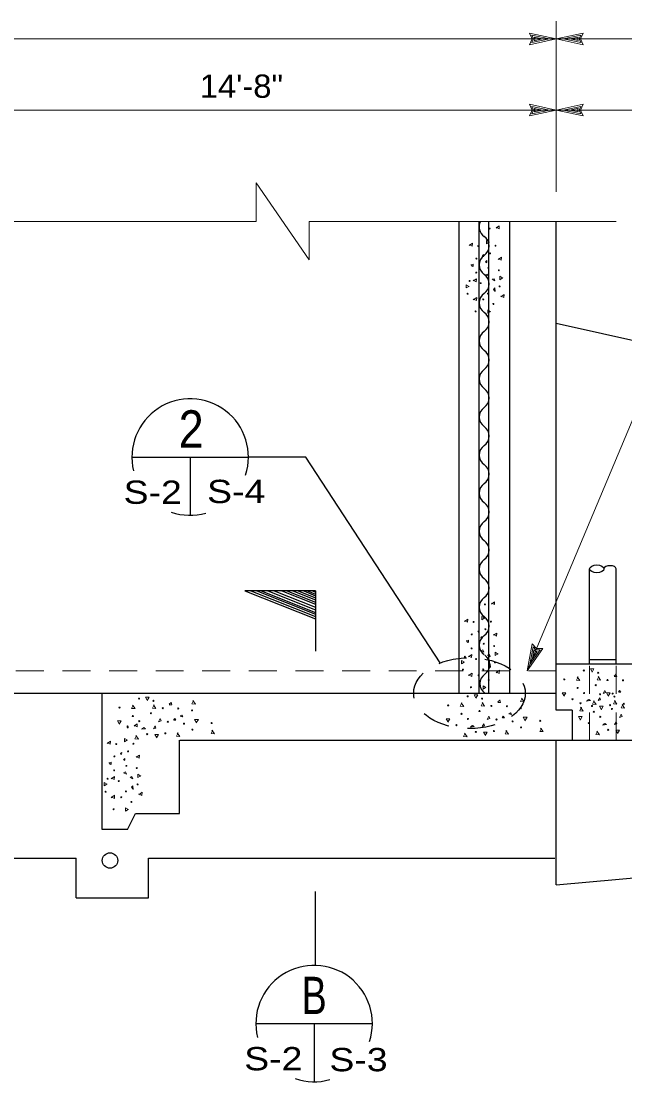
# Model space of a CAD drawing. Extents: x -22.3 to 19.7, y -11.8 to 18.2.
# Drawn here: x -3.89 to -0.65, y 0.55 to 6.24 of the extents above; entities that cross this region are included whole.
import ezdxf
from ezdxf.enums import TextEntityAlignment as Align

# ---------------------------------------------------------------- set-up
doc = ezdxf.new("R2010")
doc.units = 0
doc.header["$LTSCALE"] = 0.05
doc.linetypes.add('MEDIUM_DASHED', pattern=[4.5, 3, -1.5])
doc.layers.add('1', color=7, linetype='Continuous', lineweight=13)
doc.layers.add('2', color=7, linetype='Continuous', lineweight=13)

msp = doc.modelspace()

# ---------------------------------------------------------------- linework, layer by layer
at = {"layer": '1'}
for p, q in [((-1.02142, 5.32831), (-1.02142, 6.24331)), ((-8.42042, 6.14831), (-1.02142, 6.14831)), ((-1.02142, 6.14831), (-1.16542, 6.17931)), ((-1.02142, 6.14831), (-1.16542, 6.11731)), ((-1.05842, 6.14831), (-1.15242, 6.16831)), ((-1.14342, 6.14831), (-1.15242, 6.16831)), ((-1.05842, 6.14831), (-1.15242, 6.12831)), ((-1.15242, 6.12831), (-1.14342, 6.14831)), ((-1.09442, 6.14831), (-1.13942, 6.15731)), ((-1.13542, 6.14831), (-1.13942, 6.15731)), ((-1.09442, 6.14831), (-1.13942, 6.13831)), ((-1.13942, 6.13831), (-1.13542, 6.14831)), ((-1.02142, 6.14831), (-0.87742, 6.17931)), ((-1.02142, 6.14831), (-0.87742, 6.11731)), ((-1.02142, 6.14831), (4.89858, 6.14831)), ((-0.98442, 6.14831), (-0.89042, 6.16831)), ((-0.98442, 6.14831), (-0.89042, 6.12831)), ((-0.94842, 6.14831), (-0.90342, 6.15831)), ((-0.94842, 6.14831), (-0.90342, 6.13931)), ((-0.90342, 6.15831), (-0.90742, 6.14831)), ((-0.90742, 6.14831), (-0.90342, 6.13931)), ((-0.89042, 6.16831), (-0.89942, 6.14831)), ((-0.89942, 6.14831), (-0.89042, 6.12831)), ((-1.02142, 5.76631), (-1.16542, 5.79731)), ((-1.02142, 5.76631), (-1.16542, 5.73531)), ((-1.05842, 5.76631), (-1.15242, 5.78631)), ((-1.14342, 5.76631), (-1.15242, 5.78631)), ((-1.05842, 5.76631), (-1.15242, 5.74631)), ((-1.15242, 5.74631), (-1.14342, 5.76631)), ((-1.09442, 5.76631), (-1.13942, 5.77531)), ((-1.13542, 5.76631), (-1.13942, 5.77531)), ((-1.09442, 5.76631), (-1.13942, 5.75631)), ((-1.13942, 5.75631), (-1.13542, 5.76631)), ((-1.02142, 5.76631), (-0.87742, 5.79731)), ((-1.02142, 5.76631), (-0.87742, 5.73531)), ((-1.02142, 5.76631), (4.88358, 5.76631)), ((-0.98442, 5.76631), (-0.89042, 5.78631)), ((-0.98442, 5.76631), (-0.89042, 5.74631)), ((-0.94842, 5.76631), (-0.90342, 5.77631)), ((-0.94842, 5.76631), (-0.90342, 5.75731)), ((-0.90342, 5.77631), (-0.90742, 5.76631)), ((-0.90742, 5.76631), (-0.90342, 5.75731)), ((-0.89042, 5.78631), (-0.89942, 5.76631)), ((-0.89942, 5.76631), (-0.89042, 5.74631)), ((-2.63142, 5.16931), (-2.63142, 5.37531)), ((-2.34642, 4.96231), (-2.63142, 5.37531)), ((-4.53142, 5.16931), (-2.63142, 5.16931)), ((-2.34642, 4.96231), (-2.34642, 5.16931)), ((-2.34642, 5.16931), (-0.69942, 5.16931)), ((-1.17742, 2.75631), (-1.09342, 2.87731)), ((-1.16342, 2.79031), (-1.14542, 2.88531)), ((-1.16342, 2.79031), (-1.10842, 2.86931)), ((-1.14942, 2.82331), (-1.14142, 2.86931)), ((-1.14942, 2.82331), (-1.12342, 2.86131)), ((-1.14542, 2.88531), (-1.13042, 2.86931)), ((-1.14142, 2.86931), (-1.13342, 2.86131)), ((-1.13342, 2.86131), (-1.12342, 2.86131)), ((-1.13042, 2.86931), (-1.10842, 2.86931))]:
    msp.add_line(p, q, dxfattribs=at)
at = {"layer": '1', "lineweight": 25}
for p, q in [((-1.54242, 2.63731), (-1.54242, 5.16931)), ((-1.43542, 2.63731), (-1.43542, 5.16931)), ((-1.38242, 2.63731), (-1.38242, 5.16931)), ((-1.27142, 2.63731), (-1.27142, 5.16931)), ((-1.02142, 2.54631), (-1.02142, 5.16931)), ((-1.02142, 4.62231), (1.75058, 4.00831)), ((-0.84242, 2.79431), (-0.84242, 3.30431)), ((-0.70042, 2.79431), (-0.70042, 3.30431)), ((-1.02142, 2.79431), (0.96858, 2.79431)), ((-0.84242, 2.81831), (-0.70042, 2.81831)), ((-8.42042, 2.63731), (-1.02142, 2.63731)), ((-3.45742, 1.90531), (-3.45742, 2.63731)), ((-0.93642, 2.54631), (-1.02142, 2.54631)), ((-0.93642, 2.54631), (-0.93642, 2.38331)), ((-3.04242, 1.99231), (-3.04242, 2.38431)), ((-3.04142, 2.38431), (1.73958, 2.38431)), ((-1.02142, 1.60831), (-1.02142, 2.38431)), ((-3.32242, 1.90531), (-3.27842, 1.99231)), ((-3.27842, 1.99231), (-3.04242, 1.99231)), ((-3.32242, 1.90531), (-3.45742, 1.90531)), ((-1.02142, 1.60831), (1.74758, 1.85831)), ((-5.83442, 1.75131), (-3.59642, 1.75131)), ((-3.59642, 1.53931), (-3.59642, 1.75131)), ((-3.20842, 1.75131), (-1.02942, 1.75131)), ((-3.20842, 1.53931), (-3.20842, 1.75131)), ((-3.59642, 1.53931), (-3.20842, 1.53931))]:
    msp.add_line(p, q, dxfattribs=at)
at = {"layer": '1', "linetype": 'MEDIUM_DASHED'}
for p, q in [((-0.84242, 2.38431), (-0.84242, 2.79431)), ((-0.70042, 2.38431), (-0.70042, 2.79431)), ((-8.42042, 2.75631), (-1.02142, 2.75631))]:
    msp.add_line(p, q, dxfattribs=at)
at = {"layer": '1'}
for points in [[(-1.16542, 6.11731), (-1.15142, 6.14831), (-1.16542, 6.17931)], [(-0.87742, 6.17931), (-0.89142, 6.14831), (-0.87742, 6.11731)], [(-8.42042, 5.76631), (-4.72742, 5.76631), (-1.02142, 5.76631)], [(-1.16542, 5.73531), (-1.15142, 5.76631), (-1.16542, 5.79731)], [(-0.87742, 5.79731), (-0.89142, 5.76631), (-0.87742, 5.73531)], [(-0.18742, 5.11631), (-1.17742, 2.75631), (-1.15042, 2.90131)], [(-1.15042, 2.90131), (-1.12742, 2.87631), (-1.09342, 2.87731)]]:
    msp.add_lwpolyline(points, dxfattribs=at)
at = {"layer": '1', "lineweight": 25}
msp.add_lwpolyline([(-1.64342, 2.79931), (-2.36542, 3.90431), (-2.67342, 3.90431)], dxfattribs=at)
msp.add_circle((-3.41542, 1.73931), 0.0412, dxfattribs=at)
for centre, start, end in [((-1.37392, 5.13931), 152.03288, 235.92281), ((-1.44292, 5.03731), 304.0772, 55.92281), ((-1.37392, 4.93531), 124.0772, 235.92281), ((-1.44292, 4.83331), 304.0772, 55.92281), ((-1.37392, 4.73131), 124.0772, 235.92281), ((-1.44292, 4.62931), 304.0772, 55.92281), ((-1.37392, 4.52731), 124.0772, 235.92281), ((-1.44292, 4.42531), 304.0772, 55.92281), ((-1.37392, 4.32331), 124.0772, 235.92281), ((-1.44292, 4.22131), 304.0772, 55.92281), ((-1.37392, 4.11931), 124.0772, 235.92281), ((-1.44292, 4.01731), 304.0772, 55.92281), ((-1.37392, 3.91531), 124.0772, 235.92281), ((-1.44292, 3.81331), 304.0772, 55.92281), ((-1.37392, 3.71131), 124.0772, 235.92281), ((-1.44292, 3.60931), 304.0772, 55.92281), ((-1.37392, 3.50731), 124.0772, 235.92281), ((-1.44292, 3.40531), 304.0772, 55.92281), ((-1.37392, 3.30331), 124.0772, 235.92281), ((-1.44292, 3.20131), 304.0772, 55.92281), ((-1.37392, 3.09931), 124.0772, 235.92281), ((-1.44292, 2.99731), 304.0772, 55.92281), ((-1.37392, 2.89531), 124.0772, 235.92281), ((-1.43892, 2.79031), 304.0772, 55.92281), ((-1.36992, 2.68831), 124.0772, 235.92281)]:
    msp.add_arc(centre, 0.06157, start, end, dxfattribs=at)
msp.add_ellipse((-0.80392, 3.30431), major_axis=(0.0385, 0), ratio=0.545501, dxfattribs=at)
msp.add_ellipse((-0.73292, 3.30431), major_axis=(-0.0325, 0), ratio=0.528164, start_param=3.1415927, end_param=6.2831853, dxfattribs=at)
at = {"layer": '1', "linetype": 'MEDIUM_DASHED', "lineweight": 25}
msp.add_ellipse((-1.48692, 2.63731), major_axis=(0.2995, -0.001), ratio=0.634389, dxfattribs=at)
at = {"layer": '2'}
for p, q in [((-1.47042, 4.92631), (-1.47842, 4.93531)), ((-1.49542, 2.90931), (-1.50342, 2.91831)), ((-0.71142, 2.72931), (-0.70142, 2.73831)), ((-3.09742, 2.57831), (-3.08742, 2.58731)), ((-1.33442, 2.59031), (-1.32442, 2.59931)), ((-3.41242, 2.25431), (-3.42042, 2.26331))]:
    msp.add_line(p, q, dxfattribs=at)
at = {"layer": '2', "lineweight": 25}
for p, q in [((-3.29742, 3.90431), (-2.67342, 3.90431)), ((-2.98542, 3.90431), (-2.98542, 3.59231)), ((-2.66042, 3.18631), (-2.31242, 3.04831)), ((-2.62742, 3.18631), (-2.31242, 3.06131)), ((-2.60442, 3.18631), (-2.31242, 3.07031)), ((-2.56842, 3.18631), (-2.31242, 3.08431)), ((-2.53442, 3.18631), (-2.31242, 3.09831)), ((-2.49342, 3.18631), (-2.31242, 3.11431)), ((-2.46642, 3.18631), (-2.31242, 3.12531)), ((-2.43442, 3.18631), (-2.31242, 3.13731)), ((-2.40542, 3.18631), (-2.31242, 3.14931)), ((-2.37642, 3.18631), (-2.31242, 3.16031)), ((-2.35642, 3.18631), (-2.31242, 3.16831)), ((-2.32942, 3.18631), (-2.31242, 3.17931)), ((-2.31242, 3.18631), (-2.31242, 2.86231)), ((-2.31242, 1.17831), (-2.31242, 1.57331)), ((-2.63242, 0.86431), (-2.00842, 0.86431)), ((-2.32042, 0.86431), (-2.32042, 0.55231))]:
    msp.add_line(p, q, dxfattribs=at)
at = {"layer": '2'}
for points in [[(-1.34442, 5.13731), (-1.32842, 5.12931), (-1.32742, 5.14531), (-1.34442, 5.13231)], [(-1.38342, 5.05731), (-1.39642, 5.04831), (-1.39642, 5.06631), (-1.37942, 5.05731)], [(-1.48842, 5.04331), (-1.47242, 5.03531), (-1.47042, 5.05231), (-1.48842, 5.03931)], [(-1.41442, 4.97931), (-1.41742, 4.98731), (-1.40942, 4.99131), (-1.41242, 4.97931)], [(-1.39342, 4.94731), (-1.40142, 4.95231), (-1.39342, 4.95831), (-1.39342, 4.94931)], [(-1.33242, 4.96831), (-1.31642, 4.96031), (-1.31442, 4.97631), (-1.33242, 4.96531)], [(-1.48042, 4.93531), (-1.46742, 4.93931), (-1.46742, 4.92631)], [(-1.46742, 4.85331), (-1.45142, 4.84531), (-1.44942, 4.86131), (-1.46742, 4.84931)], [(-1.31142, 4.86431), (-1.32442, 4.85631), (-1.32442, 4.87431), (-1.30742, 4.86431)], [(-1.49042, 4.82031), (-1.50442, 4.81231), (-1.50442, 4.82931), (-1.48842, 4.82031)], [(-1.35142, 4.79531), (-1.35742, 4.80431), (-1.35142, 4.81231), (-1.34842, 4.79231)], [(-1.46642, 4.75231), (-1.44942, 4.74431), (-1.44842, 4.76131), (-1.46642, 4.74831)], [(-1.31942, 4.76831), (-1.30342, 4.76031), (-1.30142, 4.77731), (-1.31942, 4.76431)], [(-1.37542, 4.68431), (-1.38942, 4.67631), (-1.38942, 4.69431), (-1.37342, 4.68431)], [(-1.36942, 3.12031), (-1.35342, 3.11231), (-1.35242, 3.12831), (-1.36942, 3.11531)], [(-1.51342, 3.02631), (-1.49742, 3.01831), (-1.49542, 3.03531), (-1.51342, 3.02231)], [(-1.40842, 3.04031), (-1.42142, 3.03131), (-1.42142, 3.04931), (-1.40442, 3.04031)], [(-1.43942, 2.96231), (-1.44242, 2.97031), (-1.43442, 2.97431), (-1.43742, 2.96231)], [(-1.50542, 2.91831), (-1.49242, 2.92231), (-1.49242, 2.90931)], [(-1.41842, 2.93031), (-1.42642, 2.93531), (-1.41842, 2.94131), (-1.41842, 2.93231)], [(-1.35742, 2.95131), (-1.34142, 2.94331), (-1.33942, 2.95931), (-1.35742, 2.94831)], [(-1.33642, 2.84731), (-1.34942, 2.83931), (-1.34942, 2.85731), (-1.33242, 2.84731)], [(-1.51542, 2.80331), (-1.52942, 2.79531), (-1.52942, 2.81231), (-1.51342, 2.80331)], [(-1.49242, 2.83631), (-1.47642, 2.82831), (-1.47442, 2.84431), (-1.49242, 2.83231)], [(-1.37642, 2.77831), (-1.38242, 2.78731), (-1.37642, 2.79531), (-1.37342, 2.77531)], [(-1.49142, 2.73531), (-1.47442, 2.72731), (-1.47342, 2.74431), (-1.49142, 2.73131)], [(-1.34442, 2.75131), (-1.32842, 2.74331), (-1.32642, 2.76031), (-1.34442, 2.74731)], [(-0.82942, 2.75131), (-0.83842, 2.76731), (-0.81942, 2.76731), (-0.82942, 2.74931)], [(-0.70142, 2.74031), (-0.69742, 2.72631), (-0.71142, 2.72631)], [(-1.40042, 2.66731), (-1.41442, 2.65931), (-1.41442, 2.67731), (-1.39842, 2.66731)], [(-0.90442, 2.72431), (-0.91342, 2.70631), (-0.89442, 2.70531), (-0.90942, 2.72431)], [(-0.79242, 2.72631), (-0.80142, 2.70831), (-0.78342, 2.70631), (-0.79642, 2.72631)], [(-1.45242, 2.61231), (-1.46142, 2.62831), (-1.44242, 2.62831), (-1.45242, 2.61031)], [(-0.98042, 2.62431), (-0.98942, 2.63931), (-0.96942, 2.63931), (-0.98042, 2.62131)], [(-0.74242, 2.62331), (-0.75142, 2.63931), (-0.73242, 2.63931), (-0.74242, 2.62131)], [(-0.68842, 2.64331), (-0.68242, 2.65231), (-0.67542, 2.64331), (-0.68642, 2.64331)], [(-3.29042, 2.57331), (-3.29942, 2.55531), (-3.28042, 2.55431), (-3.29542, 2.57331)], [(-3.21542, 2.60031), (-3.22442, 2.61631), (-3.20542, 2.61631), (-3.21542, 2.59831)], [(-3.17842, 2.57531), (-3.18742, 2.55731), (-3.16942, 2.55531), (-3.18242, 2.57531)], [(-3.08742, 2.58931), (-3.08342, 2.57531), (-3.09742, 2.57531)], [(-2.96742, 2.59831), (-2.97642, 2.58031), (-2.95742, 2.57831), (-2.97142, 2.59831)], [(-1.52742, 2.58531), (-1.53642, 2.56731), (-1.51742, 2.56631), (-1.53242, 2.58531)], [(-1.41542, 2.58731), (-1.42442, 2.56931), (-1.40642, 2.56731), (-1.41942, 2.58731)], [(-1.32442, 2.60131), (-1.32042, 2.58731), (-1.33442, 2.58731)], [(-1.20442, 2.61031), (-1.21342, 2.59231), (-1.19442, 2.59031), (-1.20842, 2.61031)], [(-0.88642, 2.56131), (-0.89542, 2.54331), (-0.87642, 2.54131), (-0.89142, 2.56131)], [(-0.85642, 2.59731), (-0.84742, 2.60331), (-0.83842, 2.59731), (-0.86042, 2.59431)], [(-0.81742, 2.59631), (-0.82642, 2.57831), (-0.80742, 2.57731), (-0.82242, 2.59631)], [(-0.78042, 2.55231), (-0.78942, 2.56731), (-0.76942, 2.56731), (-0.78042, 2.54831)], [(-0.70542, 2.59831), (-0.71442, 2.58031), (-0.69642, 2.57831), (-0.70942, 2.59831)], [(-0.66442, 2.57631), (-0.67342, 2.55831), (-0.65542, 2.55631), (-0.66842, 2.57631)], [(-3.03842, 2.51631), (-3.02942, 2.51931), (-3.02542, 2.51031), (-3.03842, 2.51431)], [(-1.31142, 2.50431), (-1.30542, 2.51331), (-1.29842, 2.50431), (-1.30942, 2.50431)], [(-1.27542, 2.52831), (-1.26642, 2.53131), (-1.26242, 2.52231), (-1.27542, 2.52631)], [(-1.18942, 2.49331), (-1.19842, 2.50831), (-1.17842, 2.50831), (-1.18942, 2.48931)], [(-0.89342, 2.49631), (-0.90242, 2.51131), (-0.88242, 2.51131), (-0.89342, 2.49331)], [(-3.36642, 2.47331), (-3.37542, 2.48831), (-3.35542, 2.48831), (-3.36642, 2.47031)], [(-3.28642, 2.46531), (-3.27042, 2.45731), (-3.26942, 2.47331), (-3.28642, 2.46031)], [(-3.24242, 2.44631), (-3.23342, 2.45231), (-3.22442, 2.44631), (-3.24642, 2.44331)], [(-3.07442, 2.49231), (-3.06842, 2.50131), (-3.06142, 2.49231), (-3.07242, 2.49231)], [(-2.95242, 2.48131), (-2.96142, 2.49631), (-2.94142, 2.49631), (-2.95242, 2.47731)], [(-1.60342, 2.48531), (-1.61242, 2.50031), (-1.59242, 2.50031), (-1.60342, 2.48231)], [(-1.47942, 2.45831), (-1.47042, 2.46431), (-1.46142, 2.45831), (-1.48342, 2.45531)], [(-1.10042, 2.45031), (-1.10942, 2.43231), (-1.09142, 2.43131), (-1.10542, 2.45031)], [(-0.76942, 2.46931), (-0.76042, 2.47531), (-0.75142, 2.46931), (-0.77342, 2.46631)], [(-3.32542, 2.38531), (-3.33842, 2.37631), (-3.33842, 2.39431), (-3.32142, 2.38531)], [(-3.27242, 2.41031), (-3.28142, 2.39231), (-3.26242, 2.39031), (-3.27742, 2.41031)], [(-3.16642, 2.40131), (-3.17542, 2.41631), (-3.15542, 2.41631), (-3.16642, 2.39731)], [(-3.05042, 2.42531), (-3.05942, 2.40731), (-3.04142, 2.40531), (-3.05442, 2.42531)], [(-2.86342, 2.43831), (-2.87242, 2.42031), (-2.85442, 2.41931), (-2.86842, 2.43831)], [(-1.50942, 2.42231), (-1.51842, 2.40431), (-1.49942, 2.40231), (-1.51442, 2.42231)], [(-1.40342, 2.41331), (-1.41242, 2.42831), (-1.39242, 2.42831), (-1.40342, 2.40931)], [(-1.28742, 2.43731), (-1.29642, 2.41931), (-1.27842, 2.41731), (-1.29142, 2.43731)], [(-0.79942, 2.43331), (-0.80842, 2.41531), (-0.78942, 2.41331), (-0.80442, 2.43331)], [(-0.69342, 2.42431), (-0.70242, 2.43931), (-0.68242, 2.43931), (-0.69342, 2.42031)], [(-3.43042, 2.37131), (-3.41442, 2.36331), (-3.41242, 2.38031), (-3.43042, 2.36731)], [(-3.35642, 2.30731), (-3.35942, 2.31531), (-3.35142, 2.31931), (-3.35442, 2.30731)], [(-3.33542, 2.27531), (-3.34342, 2.28031), (-3.33542, 2.28631), (-3.33542, 2.27731)], [(-3.27442, 2.29631), (-3.25842, 2.28831), (-3.25642, 2.30431), (-3.27442, 2.29331)], [(-3.42242, 2.26331), (-3.40942, 2.26731), (-3.40942, 2.25431)], [(-3.40942, 2.18131), (-3.39342, 2.17331), (-3.39142, 2.18931), (-3.40942, 2.17731)], [(-3.25342, 2.19231), (-3.26642, 2.18431), (-3.26642, 2.20231), (-3.24942, 2.19231)], [(-3.43242, 2.14831), (-3.44642, 2.14031), (-3.44642, 2.15731), (-3.43042, 2.14831)], [(-3.29342, 2.12331), (-3.29942, 2.13231), (-3.29342, 2.14031), (-3.29042, 2.12031)], [(-3.40842, 2.08031), (-3.39142, 2.07231), (-3.39042, 2.08931), (-3.40842, 2.07631)], [(-3.26142, 2.09631), (-3.24542, 2.08831), (-3.24342, 2.10531), (-3.26142, 2.09231)], [(-3.31742, 2.01231), (-3.33142, 2.00431), (-3.33142, 2.02231), (-3.31542, 2.01231)]]:
    msp.add_lwpolyline(points, dxfattribs=at)
for points in [[(-1.38542, 4.87431), (-1.40142, 4.88231), (-1.39042, 4.88631)], [(-1.35142, 4.84931), (-1.36542, 4.85831), (-1.35542, 4.86131)], [(-1.41042, 2.85731), (-1.42642, 2.86531), (-1.41542, 2.86931)], [(-1.37642, 2.83231), (-1.39042, 2.84131), (-1.38042, 2.84431)], [(-0.76942, 2.63531), (-0.76042, 2.65231), (-0.75542, 2.64031)], [(-0.79642, 2.59731), (-0.78742, 2.61231), (-0.78342, 2.60131)], [(-1.39242, 2.49631), (-1.38342, 2.51331), (-1.37842, 2.50131)], [(-0.68242, 2.50731), (-0.67342, 2.52431), (-0.66842, 2.51231)], [(-3.18242, 2.44631), (-3.17342, 2.46131), (-3.16942, 2.45031)], [(-3.15542, 2.48431), (-3.14642, 2.50131), (-3.14142, 2.48931)], [(-1.41942, 2.45831), (-1.41042, 2.47331), (-1.40642, 2.46231)], [(-0.70942, 2.46931), (-0.70042, 2.48431), (-0.69642, 2.47331)], [(-3.32742, 2.20231), (-3.34342, 2.21031), (-3.33242, 2.21431)], [(-3.29342, 2.17731), (-3.30742, 2.18631), (-3.29742, 2.18931)]]:
    msp.add_lwpolyline(points, close=True, dxfattribs=at)
at = {"layer": '2', "lineweight": 25}
msp.add_lwpolyline([(-2.31242, 3.18631), (-2.69142, 3.18631), (-2.31242, 3.03631)], dxfattribs=at)
at = {"layer": '2'}
for centre, radius in [((-1.379, 5.13079), 0.00263), ((-1.44015, 5.03643), 0.00263), ((-1.34741, 5.03805), 0.00263), ((-1.44947, 4.9696), 0.00263), ((-1.37616, 4.99714), 0.00263), ((-1.45109, 4.89468), 0.00263), ((-1.38548, 4.91938), 0.00263), ((-1.32959, 4.90723), 0.00263), ((-1.48632, 4.84972), 0.00263), ((-1.42638, 4.83757), 0.00263), ((-1.49726, 4.78047), 0.00263), ((-1.38831, 4.78168), 0.00263), ((-1.32554, 4.81975), 0.00263), ((-1.41302, 4.7505), 0.00263), ((-1.35834, 4.72579), 0.00263), ((-1.45392, 4.6861), 0.00263), ((-1.404, 3.11379), 0.00263), ((-1.46515, 3.01943), 0.00263), ((-1.37241, 3.02105), 0.00263), ((-1.40116, 2.98014), 0.00263), ((-1.47447, 2.9526), 0.00263), ((-1.41048, 2.90238), 0.00263), ((-1.47609, 2.87768), 0.00263), ((-1.35459, 2.89023), 0.00263), ((-1.51132, 2.83272), 0.00263), ((-1.45138, 2.82057), 0.00263), ((-1.35054, 2.80275), 0.00263), ((-1.52226, 2.76347), 0.00263), ((-1.43802, 2.7335), 0.00263), ((-1.41331, 2.76468), 0.00263), ((-0.87347, 2.75914), 0.00293), ((-0.79652, 2.74699), 0.00293), ((-1.38334, 2.70879), 0.00263), ((-0.97832, 2.71099), 0.00293), ((-0.81002, 2.68039), 0.00293), ((-0.74657, 2.70784), 0.00293), ((-0.66332, 2.70604), 0.00293), ((-1.49647, 2.62014), 0.00293), ((-1.47892, 2.6691), 0.00263), ((-0.90677, 2.66554), 0.00293), ((-0.87212, 2.63809), 0.00293), ((-0.78647, 2.63114), 0.00293), ((-0.71912, 2.63494), 0.00293), ((-0.70952, 2.61899), 0.00293), ((-3.36432, 2.55999), 0.00293), ((-3.25947, 2.60814), 0.00293), ((-3.18252, 2.59599), 0.00293), ((-1.60132, 2.57199), 0.00293), ((-1.41952, 2.60799), 0.00293), ((-1.36957, 2.56884), 0.00293), ((-1.28632, 2.56704), 0.00293), ((-0.93422, 2.60479), 0.00293), ((-0.89132, 2.58299), 0.00293), ((-0.82982, 2.56834), 0.00293), ((-0.73262, 2.57284), 0.00293), ((-0.65957, 2.57984), 0.00293), ((-3.29277, 2.51454), 0.00293), ((-3.19602, 2.52939), 0.00293), ((-3.13257, 2.55684), 0.00293), ((-3.04932, 2.55504), 0.00293), ((-2.97507, 2.54469), 0.00293), ((-1.52977, 2.52654), 0.00293), ((-1.43302, 2.54139), 0.00293), ((-1.21207, 2.55669), 0.00293), ((-0.81977, 2.53754), 0.00293), ((-0.78512, 2.51009), 0.00293), ((-0.72302, 2.55239), 0.00293), ((-3.321, 2.45879), 0.00263), ((-3.32022, 2.45379), 0.00293), ((-3.25812, 2.48709), 0.00293), ((-3.10512, 2.48394), 0.00293), ((-3.01872, 2.47359), 0.00293), ((-2.87022, 2.47674), 0.00293), ((-1.55722, 2.46579), 0.00293), ((-1.49512, 2.49909), 0.00293), ((-1.34212, 2.49594), 0.00293), ((-1.25572, 2.48559), 0.00293), ((-1.21027, 2.45364), 0.00293), ((-1.10722, 2.48874), 0.00293), ((-0.84722, 2.47679), 0.00293), ((-3.21582, 2.41734), 0.00293), ((-3.11862, 2.42184), 0.00293), ((-2.97327, 2.44164), 0.00293), ((-1.45282, 2.42934), 0.00293), ((-1.35562, 2.43384), 0.00293), ((-0.74282, 2.44034), 0.00293), ((-3.38215, 2.36443), 0.00263), ((-3.28941, 2.36605), 0.00263), ((-3.39147, 2.2976), 0.00263), ((-3.31816, 2.32514), 0.00263), ((-3.39309, 2.22268), 0.00263), ((-3.32748, 2.24738), 0.00263), ((-3.27159, 2.23523), 0.00263), ((-3.42832, 2.17772), 0.00263), ((-3.36838, 2.16557), 0.00263), ((-3.43926, 2.10847), 0.00263), ((-3.33031, 2.10968), 0.00263), ((-3.26754, 2.14775), 0.00263), ((-3.35502, 2.0785), 0.00263), ((-3.30034, 2.05379), 0.00263), ((-3.39592, 2.0141), 0.00263)]:
    msp.add_circle(centre, radius, dxfattribs=at)
at = {"layer": '2', "lineweight": 25}
for centre, start, end in [((-2.98542, 3.90431), 341.96976, 193.81208), ((-2.98542, 3.90431), 251.04049, 285.74671), ((-2.32042, 0.86431), 341.96976, 193.81208), ((-2.32042, 0.86431), 251.04049, 285.74671)]:
    msp.add_arc(centre, 0.3125, start, end, dxfattribs=at)

# ---------------------------------------------------------------- texts
at = {"layer": '1', "width": 1.05}
msp.add_text('14\'-8"', height=0.125, dxfattribs=at).set_placement((-2.71042, 5.83231), align=Align.CENTER)
at = {"layer": '2'}
for s, height, width, p in [('2', 0.2, 0.9, (-2.97992, 3.95531)), ('S-2', 0.125, 1.2, (-3.18642, 3.65331)), ('S-4', 0.125, 1.2, (-2.73842, 3.65731)), ('B', 0.2, 0.75, (-2.31992, 0.91531)), ('S-2', 0.125, 1.2, (-2.53942, 0.61331)), ('S-3', 0.125, 1.2, (-2.08242, 0.60831))]:
    msp.add_text(s, height=height, dxfattribs=dict(at, width=width)).set_placement(p, align=Align.CENTER)

doc.saveas('drawing.dxf')
